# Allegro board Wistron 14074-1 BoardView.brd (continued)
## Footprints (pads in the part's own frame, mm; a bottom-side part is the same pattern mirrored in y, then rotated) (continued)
BSH-03001-FDA
  round 0.254 hole 1.016 unplated: (-10.065,0) (10.065,0)
  rect 0.279x2.769 smd: 1(-7.25,-5.526) 2(-7.25,0.198) 3(-6.75,-5.526) 4(-6.75,0.198) 5(-6.25,-5.526) 6(-6.25,0.198) 7(-5.751,-5.526) 8(-5.751,0.198) 9(-5.25,-5.526) 10(-5.25,0.198) 11(-4.75,-5.526) 12(-4.75,0.198) 13(-4.249,-5.526) 14(-4.249,0.198) 15(-3.75,-5.526) 16(-3.75,0.198) 17(-3.25,-5.526) 18(-3.25,0.198) 19(-2.75,-5.526) 20(-2.75,0.198) 21(-2.25,-5.526) 22(-2.25,0.198) 23(-1.75,-5.526) 24(-1.75,0.198) 25(-1.25,-5.526) 26(-1.25,0.198) 27(-0.751,-5.526) 28(-0.751,0.198) 29(-0.25,-5.526) 30(-0.25,0.198) 31(0.25,-5.526) 32(0.25,0.198) 33(0.751,-5.526) 34(0.751,0.198) 35(1.25,-5.526) 36(1.25,0.198) 37(1.75,-5.526) 38(1.75,0.198) 39(2.25,-5.526) 40(2.25,0.198) 41(2.75,-5.526) 42(2.75,0.198) 43(3.25,-5.526) 44(3.25,0.198) 45(3.75,-5.526) 46(3.75,0.198) 47(4.249,-5.526) 48(4.249,0.198) 49(4.75,-5.526) 50(4.75,0.198) 51(5.25,-5.526) 52(5.25,0.198) 53(5.751,-5.526) 54(5.751,0.198) 55(6.25,-5.526) 56(6.25,0.198) 57(6.75,-5.526) 58(6.75,0.198) 59(7.25,-5.526) 60(7.25,0.198)
C402-TO0D2H26
  custom 0.152x0.152 smd: 1(0,0.457) 2(0,-0.457)
C402H20
  custom 0.152x0.152 smd: 1(0,0.445) 2(0,-0.445)
C402H22
  custom 0.152x0.152 smd: 1(0,0.445) 2(0,-0.445)
C402H24
  custom 0.152x0.152 smd: 1(0,0.445) 2(0,-0.445)
C603
  custom 0.216x0.216 smd: 1(0,0.762) 2(0,-0.762)
C603H36
  custom 0.216x0.216 smd: 1(0,0.762) 2(0,-0.762)
C603H38
  custom 0.216x0.216 smd: 1(0,0.762) 2(0,-0.762)
C603H40
  custom 0.216x0.216 smd: 1(0,0.762) 2(0,-0.762)
C805H54
  rect 1.397x1.143 smd: 1(0,0.965) 2(0,-0.965)
C805H56
  rect 1.397x1.143 smd: 1(0,0.965) 2(0,-0.965)
C805H58
  rect 1.397x1.143 smd: 1(0,0.965) 2(0,-0.965)
C4201WV0-B2X12P
  round 2.184 hole 1.422: 1(-23.1,2.75) 2(-18.9,2.75) 3(-14.7,2.75) 4(-10.5,2.75) 5(-6.3,2.75) 6(-2.1,2.75) 7(2.1,2.75) 8(6.3,2.75) 9(10.5,2.75) 10(14.7,2.75) 11(18.9,2.75) 12(23.1,2.75) 13(-23.1,-2.75) 14(-18.9,-2.75) 15(-14.7,-2.75) 16(-10.5,-2.75) 17(-6.3,-2.75) 18(-2.1,-2.75) 19(2.1,-2.75) 20(6.3,-2.75) 21(10.5,-2.75) 22(14.7,-2.75) 23(18.9,-2.75) 24(23.1,-2.75)
CON2C
  custom 0.171x0.171 smd: 1(0,0.533) 2(0,-0.533)
CON2O-U
  custom 0.159x0.159 smd: 1(0,0.254) 2(0,-0.254)
CT7343H83
  rect 2.413x2.286 smd: 1(0,3.15) 2(0,-3.15)
D1608AK-UH28
  rect 0.559x0.711 smd: A(0,0.889) K(0,-0.889)
D5436AKH97
  rect 2.286x2.032 smd: A(0,2.438) K(0,-2.438)
DFN10G3-G265175H32
  rect 0.305x0.914 smd: 1(1,1.549) 2(0.5,1.549) 3(0,1.549) 4(-0.5,1.549) 5(-1,1.549) 6(-1,-1.549) 7(-0.5,-1.549) 8(0,-1.549) 9(0.5,-1.549) 10(1,-1.549)
  rect 2.642x1.753 smd: 11(0,0)
DFN10G2510H26
  rect 0.305x0.787 smd: 1(1,0.494) 5(-1,0.494) 6(-1,-0.494) 10(1,-0.494)
  rect 0.254x0.787 smd: 2(0.521,0.494) 4(-0.521,0.494) 7(-0.521,-0.494) 9(0.521,-0.494)
  rect 0.025x0.025 smd: 3(0,0.494)
  rect 0.406x1.753 smd: 8(0,-0.494)
DZ11AA1-H5W7-4F
  round 1.448 hole 1.041: 1(-4.326,-2) 2(-2.036,-2) 3(0.254,-2) 4(2.544,-2) 5(4.834,-2) 6(-5.471,0) 7(-3.181,0) 8(-0.892,0) 9(1.4,0) 10(3.689,0) 11(-4.326,2) 12(-2.036,2) 13(0.254,2) 14(2.544,2) 15(4.834,2)
  round 3.454 hole 3.048: 16(-12.496,0) 17(12.496,0)
ECAP-80D5H493
  rect 1.397x1.397 hole 0.991: 1(0,-1.016)
  round 1.397 hole 0.991: 2(0,1.016)
ECAP-100D6D3H237
  rect 1.397x1.397 hole 0.991: 1(0,-1.27)
  round 1.397 hole 0.991: 2(0,1.27)
ECAP-100D6D3H375
  rect 1.397x1.397 hole 0.991: 1(0,-1.27)
  round 1.397 hole 0.991: 2(0,1.27)
ECAP-100D6D3H473
  rect 1.397x1.397 hole 0.991: 1(0,-1.27)
  round 1.397 hole 0.991: 2(0,1.27)
ECAP-138D8-UH355
  rect 1.397x1.397 hole 0.991: 1(0,-1.75)
  round 1.397 hole 0.991: 2(0,1.75)
GAP-CLOSE-PWR-3
  rect 0.66x0.762 smd: 1(-0.305,0) 2(0.305,0)
GENS315R158-8-F-A
  round 0.254 hole 4.013 unplated: (0,0)
  round 0.864 hole 0.508: 1(-0.634,3.189) 2(-2.703,1.806) 3(-3.189,-0.634) 4(-1.806,-2.703) 5(0.634,-3.189) 6(2.703,-1.806) 7(3.189,0.634) 8(1.806,2.703)
HF1004E
  round 1.549 hole 1.143: 1(3.81,0) 2(1.27,0) 3(-1.27,0) 4(-3.81,0)
L603H38
  custom 0.216x0.216 smd: 1(0,0.762) 2(0,-0.762)
L3030-3009-2H40
  rect 3.251x1.524 smd: 1(0,1.108) 2(0,-1.108)
L125100-4P-1H28
  rect 0.762x0.432 smd: 1(0.625,0.341) 2(-0.625,0.341) 3(-0.625,-0.341) 4(0.625,-0.341)
L125100-4P-4H24
  rect 0.762x0.432 smd: 1(-0.625,0.341) 2(0.625,0.341) 3(0.625,-0.341) 4(-0.625,-0.341)
L125100-4P-5H24
  rect 0.457x0.838 smd: 1(-0.326,0.587) 2(0.326,0.587) 3(-0.326,-0.587) 4(0.326,-0.587)
L686647-127318H119
  rect 3.683x2.413 smd: 1(0,2.986) 2(0,-2.986)
LFDFN10G3-G2619H40
  rect 0.305x0.508 smd: 1(1,1.551) 2(0.5,1.551) 3(0,1.551) 4(-0.5,1.551) 5(-1,1.551) 6(-1,-1.551) 7(-0.5,-1.551) 8(0,-1.551) 9(0.5,-1.551) 10(1,-1.551)
  rect 2.591x1.778 smd: 11(0,0)
LFQFN28J4-G2D7-UH40
  rect 0.203x0.584 smd: 1(1.2,1.86) 2(0.8,1.86) 3(0.4,1.86) 4(0,1.86) 5(-0.4,1.86) 6(-0.8,1.86) 7(-1.2,1.86) 15(-1.2,-1.86) 16(-0.8,-1.86) 17(-0.4,-1.86) 18(0,-1.86) 19(0.4,-1.86) 20(0.8,-1.86) 21(1.2,-1.86)
  rect 0.584x0.203 smd: 8(-1.86,1.2) 9(-1.86,0.8) 10(-1.86,0.4) 11(-1.86,0) 12(-1.86,-0.4) 13(-1.86,-0.8) 14(-1.86,-1.2) 22(1.86,-1.2) 23(1.86,-0.8) 24(1.86,-0.4) 25(1.86,0) 26(1.86,0.4) 27(1.86,0.8) 28(1.86,1.2)
  rect 2.692x2.692 smd: 29(0,0)
LQFP64H63
  rect 0.203x1.524 smd: 1(3,4.242) 2(2.6,4.242) 3(2.2,4.242) 4(1.8,4.242) 5(1.4,4.242) 6(0.999,4.242) 7(0.599,4.242) 8(0.199,4.242) 9(-0.199,4.242) 10(-0.599,4.242) 11(-0.999,4.242) 12(-1.4,4.242) 13(-1.8,4.242) 14(-2.2,4.242) 15(-2.6,4.242) 16(-3,4.242) 33(-3,-4.242) 34(-2.6,-4.242) 35(-2.2,-4.242) 36(-1.8,-4.242) 37(-1.4,-4.242) 38(-0.999,-4.242) 39(-0.599,-4.242) 40(-0.199,-4.242) 41(0.199,-4.242) 42(0.599,-4.242) 43(0.999,-4.242) 44(1.4,-4.242) 45(1.8,-4.242) 46(2.2,-4.242) 47(2.6,-4.242) 48(3,-4.242)
  rect 1.524x0.203 smd: 17(-4.242,3) 18(-4.242,2.6) 19(-4.242,2.2) 20(-4.242,1.8) 21(-4.242,1.4) 22(-4.242,0.999) 23(-4.242,0.599) 24(-4.242,0.199) 25(-4.242,-0.199) 26(-4.242,-0.599) 27(-4.242,-0.999) 28(-4.242,-1.4) 29(-4.242,-1.8) 30(-4.242,-2.2) 31(-4.242,-2.6) 32(-4.242,-3) 49(4.242,-3) 50(4.242,-2.6) 51(4.242,-2.2) 52(4.242,-1.8) 53(4.242,-1.4) 54(4.242,-0.999) 55(4.242,-0.599) 56(4.242,-0.199) 57(4.242,0.199) 58(4.242,0.599) 59(4.242,0.999) 60(4.242,1.4) 61(4.242,1.8) 62(4.242,2.2) 63(4.242,2.6) 64(4.242,3)
NTC-402H22-U
  custom 0.14x0.14 smd: 1(0,0.445) 2(0,-0.445)
NTC-402H24-U
  custom 0.14x0.14 smd: 1(0,0.445) 2(0,-0.445)
OSC-3225-4P-4H30
  rect 1.397x1.067 smd: 1(-1.171,-0.756) 2(1.171,-0.756) 3(1.171,0.756) 4(-1.171,0.756)
OSC-3225-4P-4H36
  rect 1.397x1.067 smd: 1(-1.171,-0.756) 2(1.171,-0.756) 3(1.171,0.756) 4(-1.171,0.756)
PFPCC48-1H63
  rect 0.305x1.524 smd: 1(2.752,4.242) 2(2.252,4.242) 3(1.751,4.242) 4(1.251,4.242) 5(0.751,4.242) 6(0.25,4.242) 7(-0.25,4.242) 8(-0.751,4.242) 9(-1.251,4.242) 10(-1.751,4.242) 11(-2.252,4.242) 12(-2.752,4.242) 25(-2.752,-4.242) 26(-2.252,-4.242) 27(-1.751,-4.242) 28(-1.251,-4.242) 29(-0.751,-4.242) 30(-0.25,-4.242) 31(0.25,-4.242) 32(0.751,-4.242) 33(1.251,-4.242) 34(1.751,-4.242) 35(2.252,-4.242) 36(2.752,-4.242)
  rect 1.524x0.305 smd: 13(-4.242,2.752) 14(-4.242,2.252) 15(-4.242,1.751) 16(-4.242,1.251) 17(-4.242,0.751) 18(-4.242,0.25) 19(-4.242,-0.25) 20(-4.242,-0.751) 21(-4.242,-1.251) 22(-4.242,-1.751) 23(-4.242,-2.252) 24(-4.242,-2.752) 37(4.242,-2.752) 38(4.242,-2.252) 39(4.242,-1.751) 40(4.242,-1.251) 41(4.242,-0.751) 42(4.242,-0.25) 43(4.242,0.25) 44(4.242,0.751) 45(4.242,1.251) 46(4.242,1.751) 47(4.242,2.252) 48(4.242,2.752)
POLYSW-2114H30
  rect 1.6x0.965 smd: 1(0,0.94) 2(0,-0.94)
PPA12635GD210F
  round 2.159 hole 1.397: 1(-18.9,2.75) 2(-14.7,2.75) 3(-10.5,2.75) 4(-6.3,2.75) 5(-2.101,2.75) 6(2.101,2.75) 7(6.3,2.75) 8(10.5,2.75) 9(14.7,2.75) 10(18.9,2.75) 11(-18.9,-2.75) 12(-14.7,-2.75) 13(-10.5,-2.75) 14(-6.3,-2.75) 15(-2.101,-2.75) 16(2.101,-2.75) 17(6.3,-2.75) 18(10.5,-2.75) 19(14.7,-2.75) 20(18.9,-2.75)
PPAK-8P-3030H40
  rect 0.406x0.914 smd: 1(-0.975,-2.251) 2(-0.325,-2.251) 3(0.325,-2.251) 4(0.975,-2.251)
  rect 3.404x2.616 smd: 5(0,0)
  rect 0.025x0.025 smd: 6(1.079,0.851) 7(-0.368,0.876) 8(-1.13,0.838)
PPAK-8P-3232H40
  rect 0.406x0.914 smd: 1(-0.975,-2.396) 2(-0.325,-2.396) 3(0.325,-2.396) 4(0.975,-2.396)
  rect 3.353x2.692 smd: 5(0,0)
  rect 0.025x0.025 smd: 6(0.65,0.838) 7(0,0.838) 8(-0.65,0.838)
PPAK-8P-5262H40
  rect 0.762x1.448 smd: 1(-1.905,-3.684) 2(-0.635,-3.684) 3(0.635,-3.684) 4(1.905,-3.684)
  rect 5.512x5.309 smd: 5(0,0)
  rect 0.025x0.025 smd: 6(0.635,2.146) 7(-0.635,2.146) 8(-1.905,2.146)
PU2B1B5-PRTB
  round 1.346 hole 0.94: 1(-3.5,4.63) 2(-1,4.63) 3(1,4.63) 4(3.5,4.63) 5(4,6.13) 6(2,6.13) 7(0,6.13) 8(-2,6.13) 9(-4,6.13) 10(-3.5,7.83) 11(-1,7.83) 12(1,7.83) 13(3.5,7.83) 14(4,9.33) 15(2,9.33) 16(0,9.33) 17(-2,9.33) 18(-4,9.33)
  round 2.718 hole 2.311: G1(-9.35,0) G2(9.35,0) G3(-6.57,2.63) G4(6.57,2.63) G5(-6.57,8.31) G6(6.57,8.31) G7(-9.35,11.6) G8(9.35,13.34)
  round 1.321 hole 0.914: L11(7.2,18.81) L12(4.66,18.81) L13(-4.66,18.81) L14(-7.2,18.81) R1(5.715,13.43) R2(4.445,15.97) R3(3.175,13.43) R4(1.905,15.97) R5(0.635,13.43) R6(-0.635,15.97) R7(-1.905,13.43) R8(-3.175,15.97) R9(-4.445,13.43) R10(-5.715,15.97)
QFN20-G1D75H32
  rect 0.203x0.914 smd: 1(0.8,1.551) 2(0.4,1.551) 3(0,1.551) 4(-0.4,1.551) 5(-0.8,1.551) 11(-0.8,-1.551) 12(-0.4,-1.551) 13(0,-1.551) 14(0.4,-1.551) 15(0.8,-1.551)
  rect 0.914x0.203 smd: 6(-1.551,0.8) 7(-1.551,0.4) 8(-1.551,0) 9(-1.551,-0.4) 10(-1.551,-0.8) 16(1.551,-0.8) 17(1.551,-0.4) 18(1.551,0) 19(1.551,0.4) 20(1.551,0.8)
  rect 1.753x1.753 smd: 21(0,0)
QFN28-G3D75H32
  rect 0.305x0.914 smd: 1(1.5,2.551) 2(1,2.551) 3(0.5,2.551) 4(0,2.551) 5(-0.5,2.551) 6(-1,2.551) 7(-1.5,2.551) 15(-1.5,-2.551) 16(-1,-2.551) 17(-0.5,-2.551) 18(0,-2.551) 19(0.5,-2.551) 20(1,-2.551) 21(1.5,-2.551)
  rect 0.914x0.305 smd: 8(-2.551,1.5) 9(-2.551,1) 10(-2.551,0.5) 11(-2.551,0) 12(-2.551,-0.5) 13(-2.551,-1) 14(-2.551,-1.5) 22(2.551,-1.5) 23(2.551,-1) 24(2.551,-0.5) 25(2.551,0) 26(2.551,0.5) 27(2.551,1) 28(2.551,1.5)
  rect 3.759x3.759 smd: 29(0,0)
QFN32-G3D6H40
  rect 0.305x0.914 smd: 1(1.75,2.559) 8(-1.75,2.559) 17(-1.75,-2.559) 24(1.75,-2.559)
  rect 0.305x1.016 smd: 2(1.25,2.508) 3(0.75,2.508) 4(0.25,2.508) 5(-0.25,2.508) 6(-0.75,2.508) 7(-1.25,2.508) 18(-1.25,-2.508) 19(-0.75,-2.508) 20(-0.25,-2.508) 21(0.25,-2.508) 22(0.75,-2.508) 23(1.25,-2.508)
  rect 0.914x0.305 smd: 9(-2.559,1.75) 16(-2.559,-1.75) 25(2.559,-1.75) 32(2.559,1.75)
  rect 1.016x0.305 smd: 10(-2.508,1.25) 11(-2.508,0.75) 12(-2.508,0.25) 13(-2.508,-0.25) 14(-2.508,-0.75) 15(-2.508,-1.25) 26(2.508,-1.25) 27(2.508,-0.75) 28(2.508,-0.25) 29(2.508,0.25) 30(2.508,0.75) 31(2.508,1.25)
  rect 3.556x3.556 smd: 33(0,0)
QFN32J4-G2D85H36
  rect 0.203x0.864 smd: 1(1.4,2.085) 2(1,2.085) 3(0.6,2.085) 4(0.2,2.085) 5(-0.2,2.085) 6(-0.6,2.085) 7(-1,2.085) 8(-1.4,2.085) 17(-1.4,-2.085) 18(-1,-2.085) 19(-0.6,-2.085) 20(-0.2,-2.085) 21(0.2,-2.085) 22(0.6,-2.085) 23(1,-2.085) 24(1.4,-2.085)
  rect 0.864x0.203 smd: 9(-2.085,1.4) 10(-2.085,1) 11(-2.085,0.6) 12(-2.085,0.2) 13(-2.085,-0.2) 14(-2.085,-0.6) 15(-2.085,-1) 16(-2.085,-1.4) 25(2.085,-1.4) 26(2.085,-1) 27(2.085,-0.6) 28(2.085,-0.2) 29(2.085,0.2) 30(2.085,0.6) 31(2.085,1) 32(2.085,1.4)
  rect 2.845x2.845 smd: 33(0,0)
R402H14
  custom 0.14x0.14 smd: 1(0,0.445) 2(0,-0.445)
R402H16
  custom 0.14x0.14 smd: 1(0,0.445) 2(0,-0.445)
R603H22
  custom 0.216x0.216 smd: 1(0,0.762) 2(0,-0.762)
R805H24
  rect 1.397x1.143 smd: 1(0,0.965) 2(0,-0.965)
R2512-1U1H36
  rect 3.429x2.87 smd: 1(0,2.645) 2(0,-2.645)
SC70-6H44
  rect 0.406x1.016 smd: 1(-0.65,-0.94) 2(0,-0.94) 3(0.65,-0.94) 4(0.65,0.94) 5(0,0.94) 6(-0.65,0.94)
SE361414H241
  rect 1.372x3.607 smd: 1(0,2.499) 2(0,-2.499)
SE361416H178
  rect 1.422x3.556 smd: 1(0,2.574) 2(0,-2.574)
SKT-HDMI23-150122-9
  rect 0.305x2.591 smd: 1(4.5,0.76) 2(4,0.76) 3(3.5,0.76) 4(3,0.76) 5(2.5,0.76) 6(2,0.76) 7(1.5,0.76) 8(1,0.76) 9(0.5,0.76) 10(0,0.76) 11(-0.5,0.76) 12(-1,0.76) 13(-1.5,0.76) 14(-2,0.76) 15(-2.5,0.76) 16(-3,0.76) 17(-3.5,0.76) 18(-4,0.76) 19(-4.5,0.76)
  oval 1.626x3.429 hole 0.914x2.718: 20(7.25,0) 21(-7.25,0)
  oval 1.626x2.819 hole 0.914x2.108: 22(7.25,-5.96) 23(-7.25,-5.96)
SKT-SOIC8-092117H235
  rect 0.508x1.702 smd: 1(1.905,4.1) 2(0.635,4.1) 3(-0.635,4.1) 4(-1.905,4.1) 5(-1.905,-4.1) 6(-0.635,-4.1) 7(0.635,-4.1) 8(1.905,-4.1)
SKT-USB12-157183
  round 1.346 hole 0.94: 1(-3.5,2.71) 2(-1,2.71) 3(1,2.71) 4(3.5,2.71) 5(-3.5,5.33) 6(-1,5.33) 7(1,5.33) 8(3.5,5.33)
  round 2.718 hole 2.311: 9(-6.57,0) 10(6.57,0) 11(-6.57,5.68) 12(6.57,5.68)
SMD49-6914-0403H56
  rect 1.168x0.559 smd: 1(-3.38,-0.427) 2(3.38,-0.427) 3(3.38,0.427) 4(-3.38,0.427)
SMD-ARES4H18
  rect 0.356x0.66 smd: 1(-0.325,-0.599) 2(0.325,-0.599) 3(0.325,0.599) 4(-0.325,0.599)
SMD-ARES4H20
  rect 0.356x0.66 smd: 1(-0.325,-0.599) 2(0.325,-0.599) 3(0.325,0.599) 4(-0.325,0.599)
SMD-OSC8H52
  rect 1.803x1.6 smd: 1(-1.469,-1.4) 2(1.469,-1.4) 3(1.469,1.4) 4(-1.469,1.4)
SMD-TO-252-4H100
  rect 1.6x2.997 smd: 1(-2.286,0) 3(2.286,0)
  rect 6.756x6.756 smd: 2(0,6.807)
SMD-TO-252-DGS6698H99
  rect 6.172x5.588 smd: D(0,6.808)
  rect 1.295x2.438 smd: G(-2.35,0) S(2.35,0)
SOD323AKH38
  rect 0.559x1.016 smd: A(0,1.143) K(0,-1.143)
SOD323AKH40
  rect 0.559x1.016 smd: A(0,1.143) K(0,-1.143)
SOD882-10D6-1H20
  custom 0.114x0.114 smd: 1(0,0.445) 2(0,-0.445)
SOIC8-1H86
  rect 0.635x1.651 smd: 1(-1.905,-3.493) 2(-0.635,-3.493) 3(0.635,-3.493) 4(1.905,-3.493) 5(1.905,3.493) 6(0.635,3.493) 7(-0.635,3.493) 8(-1.905,3.493)
SOIC8-G3530H63
  rect 0.635x1.651 smd: 1(-1.905,-2.555) 2(-0.635,-2.555) 3(0.635,-2.555) 4(1.905,-2.555) 5(1.905,2.555) 6(0.635,2.555) 7(-0.635,2.555) 8(-1.905,2.555)
  rect 3.505x2.997 smd: 9(0,0)
SOIC8H69
  rect 0.635x1.651 smd: 1(-1.905,-2.54) 2(-0.635,-2.54) 3(0.635,-2.54) 4(1.905,-2.54) 5(1.905,2.54) 6(0.635,2.54) 7(-0.635,2.54) 8(-1.905,2.54)
SON14J3020-G2610H34
  rect 0.025x0.025 smd: 1(1.2,1.105) 6(-0.8,1.105) 9(-0.8,-1.105) 14(1.2,-1.105)
  custom 0.151x0.151 smd: 2(0.8,1.105) 7(-1.2,1.105) 8(-1.2,-1.105) 13(0.8,-1.105)
  rect 0.203x0.813 smd: 3(0.4,1.105) 4(0,1.105) 5(-0.4,1.105) 10(-0.4,-1.105) 11(0,-1.105) 12(0.4,-1.105)
  rect 2.591x0.889 smd: 15(0,0)
SOT23-2D4-312H44
  custom 0.191x0.191 smd: 1(-0.984,-0.953) 2(0.984,-0.953) 3(0,0.953)
SOT23-2D4-312H46
  custom 0.191x0.191 smd: 1(-0.984,-0.953) 2(0.984,-0.953) 3(0,0.953)
SOT23-2D4-312H48
  custom 0.191x0.191 smd: 1(-0.984,-0.953) 2(0.984,-0.953) 3(0,0.953)
SOT23-8PH36
  rect 0.356x1.016 smd: 1(-0.975,-1.346) 2(-0.325,-1.346) 3(0.325,-1.346) 4(0.974,-1.346) 5(0.974,1.346) 6(0.325,1.346) 7(-0.325,1.346) 8(-0.975,1.346)
SOT23CBE2D4H44
  custom 0.191x0.191 smd: B(-0.984,-0.953) C(0,0.953) E(0.984,-0.953)
SOT23DGS2D4H44
  custom 0.191x0.191 smd: D(0,0.953) G(-0.984,-0.953) S(0.984,-0.953)
SOT23DGS2D4H48
  custom 0.191x0.191 smd: D(0,0.953) G(-0.984,-0.953) S(0.984,-0.953)
SOT23DGS2D8H50
  custom 0.254x0.254 smd: D(0,1.118) G(-1.016,-1.118) S(1.016,-1.118)
SOT-6H58
  rect 0.584x1.016 smd: 1(-0.953,-1.346) 2(0,-1.346) 3(0.953,-1.346) 4(0.953,1.346) 5(0,1.346) 6(-0.953,1.346)
SOT-23-5H52
  rect 0.508x1.524 smd: 1(-0.95,-1.143) 2(0,-1.143) 3(0.95,-1.143) 4(0.95,1.143) 5(-0.95,1.143)
SOT-23-5H56
  rect 0.508x1.524 smd: 1(-0.95,-1.143) 2(0,-1.143) 3(0.95,-1.143) 4(0.95,1.143) 5(-0.95,1.143)
SOT-23-9H44
  custom 0.178x0.178 smd: 1(-0.95,-0.999) 2(0.95,-0.999) 3(0,0.999)
SOT-23-10H44
  rect 0.762x1.143 smd: 1(-0.984,-0.953) 2(0.984,-0.953) 3(0,0.953)
SOT-363H44
  rect 0.406x1.016 smd: 1(-0.65,-0.94) 2(0,-0.94) 3(0.65,-0.94) 4(0.65,0.94) 5(0,0.94) 6(-0.65,0.94)
STF256R109H99
  round 6.502 hole 2.769: 1(0,0)
T11-0063-1A40-0-U
  round 1.422 hole 1.016: 1(7.62,1.27) 2(7.62,-1.27) 3(5.08,1.27) 4(5.08,-1.27) 5(2.54,1.27) 6(2.54,-1.27) 7(0,1.27) 8(0,-1.27) 9(-2.54,1.27) 11(-5.08,1.27) 12(-5.08,-1.27) 13(-7.62,1.27) 14(-7.62,-1.27)
  rect 0.025x0.025 smd: 10(-2.54,-1.27)
TPAD14-OP
  round 0.356 smd: 1(0,0)
TPAD24
  round 0.61 smd: 1(0,0)
TPAD28
  round 0.711 smd: 1(0,0)
unnamed#2
  round 1.016 smd: (0,0)

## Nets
3VSB_DET: R2050.1 SIO1.27
5V_DDC_HDMI11: C5601.2 D3.2 R1.1 R5601.1
5V_DDC_HDMI12: C5602.2 D3.1 ED2303.5 R2.1 R5601.2
5V_DDC_HDMI21: C5603.2 D4.2 R5602.1 R9689.1
5V_DDC_HDMI22: C5604.2 D4.1 ED2304.5 R5602.2 R9690.1
5V_DUAL: C3508.1 C3509.1 C4301.2 D2202.A ED3201.2 L2202.2 PC5035.1 PD5001.A PL4702.2 PL5002.2 PL5003.2 PL5102.2 PL5103.2 PR4701.1 PR4712.1 PR4802.2 PR4805.1 PR5013.1 PR5024.1 PR5104.1 PR5115.1 PR5209.2 PR5231.1 PU5004.12 Q3404.E Q3507.D Q3508.D Q3509.D R3418.1 R3519.2 R3520.2 R4601.1 R4611.1 R4613.1 R5002.2 R9884.1 RN5411.4(B) U2901.1 U2901.2 U2903.1 U2903.2 U3701.5 U3702.5 U3703.5 U3801.5 U4301.1 U4301.2 U4301.3 U6510.1 U6510.2 U6511.1 U6511.2
5V_DUAL_EN1: Q3512.G Q3514.D Q3516.G Q4303.3 R3522.2
5V_DUAL_EN2: Q4303.5 R3525.1
5V_DUAL_EN3: Q4303.4 Q4303.6
5V_DUAL_EN4: Q4303.2 R3526.1
5V_DUAL_EN5: C3507.1 Q3507.G R3502.1
5V_DUAL_EN6: C3504.2 C3506.1 C3508.2 C3509.2 Q3508.G Q3509.G R3501.1
5V_DUAL_EN_5VSB: Q3516.D R3501.2 R3516.2 R3524.2
5V_DUAL_EN_12V: Q3512.D R3502.2 R3521.1 R3523.1
5V_HDMI: C2301.1 C15173.1 F2301.2 HDMI1.18 HDMI2.18 R9699.2
5V_HUB: R4601.2 U4601.27
5V_S0: ATX1.4 ATX1.6 ATX1.21 ATX1.22 ATX1.23 ATX2.4 ATX2.6 ATX2.19 ATX2.20 BUZ1.1 C1902.2 C2303.1 C3507.2 C5410.1 C5415.1 C6001.2 C6003.1 D3.3 D4.3 D2402.A EC3401.1 EC3409.2 F2301.1 F2402.2 PR4428.1 PR4430.1 PR4528.1 PR4530.1 Q3401.E Q3507.S Q6514.G Q6519.G R2008.2 R3402.2 R3405.1 R3425.1 R3521.2 R6564.2 SATAP1.1 SATAP1.2 U5401.8 U5401.9
5V_S0_VGA: C2415.1 C15157.1 ED6520.5 F2402.1 R9699.1 VGA1.9
5V_SB: ATX1.9 ATX2.9 C3407.1 C3504.1 C5413.1 C5418.1 PC3601.1 PC3602.1 PR4222.2 PR4907.2 PR4909.2 PR4913.2 PR4915.2 PU3601.3 Q3508.S Q3509.S R3403.1 R3411.1 R3413.1 R3516.1 R3517.1 R3519.1 R3520.1 R3522.1 R3524.1 R4308.1 U4301.5 U4301.6 U4301.7 U4301.8 U5401.4 U5401.6 U5401.7
5VSB_CTRL#: R2048.1 R9708.2 SIO1.5
12V_S0: ATX1.10 ATX1.11 ATX2.10 C1901.2 C1909.1 C1910.1 C1911.1 C1912.1 C1913.1 C2501.1 C3301.1 C3302.1 C6002.2 C6004.1 EC3414.1 PCIE16.A2 PCIE16.A3 PCIE16.B1 PCIE16.B2 PCIE16.B3 PL4402.1 PL4502.1 PR4429.1 PR4529.1 PR5007.2 PR5008.2 PR5009.2 Q2501.E Q2502.E R2003.2 R2508.1 R2509.1 R2517.1 R3423.1 R3523.2 SATAP1.5 SATAP1.6 TC1901.1
12V_VIN: PC5007.1 PC5011.1 PC5012.1 PL5004.2 PL5007.2 PQ5003.5 PQ5003.6 PQ5003.7 PQ5003.8 PT5004.1
19V_ADP: PC4201.1 PL4403.1 PL4601.1 PL4703.2 PL4801.2 PL4901.1 PL4902.1 PL5004.1 PL5006.2 PL5007.1 PR4209.1 PR4217.2 PR4219.1 PR4220.2 PR4221.2 PR4224.2 PR4226.2 PR4434.1 PR4601.1 PU4202.8 PU4203.8 R4003.1 R4301.1 R4303.1
+3VL: PG4904.2
+5V_PWR: PC4910.1 PG4903.1 PL4904.2 PR4907.1 PR4909.1 PR4913.1 PR4915.1 PT4903.1
+5VL: PG4901.2 PR4917.1
+12V: PC5010.1 PL5005.2 PR5004.1 PR5005.1 PR5007.1 PR5008.1 PR5009.1 PR5018.2 PT5005.1
+VCCCFIOAZA_1P80: AUDIO1.9 C1102.1 C2207.1 CPU1.AF4 CPU1.AH4 R2733.2 R2734.2 R6526.2 R6532.2 R9845.2
+VCCCLKDDR_1P24_1P35: C1119.1 CPU1.AM25 R6528.1
+VCCPADCF3SI0_1P8_3P3: C1126.1 C1127.1 CPU1.E1 CPU1.E2 R6527.2 R6533.2
+VCCSFRPLLDDR_1P24_1P35: C1118.1 CPU1.AN27 R6529.1
-12V: ATX1.14 ATX2.12 EC3412.1
AGND: AUDH1.1 AUDIO1.26 AUDIO1.42 AUDR1.1 AUDR1.4 AUDR1.24 AUDR1.34 C2201.2 C2202.2 C2203.2 C2204.2 C2205.2 C2211.1 C2212.2 C2215.2 C2216.2 C2217.2 C2218.2 C2219.2 C2227.1 C2228.1 C2230.2 C2231.2 C2701.2 C2702.2 C2703.2 C2704.2 C2705.2 C2706.2 D2701.K D2702.K D2703.K D2704.3 D2705.3 D2706.3 Q2701.1 Q2701.4 Q2702.1 Q2702.4 Q2703.1 Q2703.4 Q2704.1 Q2704.4 Q2705.1 Q2705.4 R2203.2 R2213.2 R2228.2 R2230.2 R2231.2 R2709.2 R2710.2 R9798.2 R9799.2 R9800.2 R9801.2
AVDD2: AUDIO1.25 AUDIO1.38 C2202.1 C2203.1 C2204.1 C2205.1
GND: ATX1.3 ATX1.5 ATX1.7 ATX1.15 ATX1.17 ATX1.18 ATX1.19 ATX1.24 ATX2.3 ATX2.5 ATX2.7 ATX2.13 ATX2.15 ATX2.16 ATX2.17 AUDIO1.7 AUDR1.G1 AUDR1.G2 AUDR1.G3 AUDR1.G4 BT1.2 C20.2 C501.2 C502.2 C503.2 C504.2 C1001.2 C1002.2 C1003.2 C1004.2 C1005.2 C1006.2 C1007.2 C1008.2 C1009.2 C1010.2 C1011.2 C1012.2 C1013.2 C1017.2 C1018.2 C1020.2 C1022.2 C1024.2 C1025.2 C1026.2 C1027.2 C1030.2 C1031.2 C1032.2 C1033.2 C1034.2 C1035.2 C1037.2 C1040.2 C1041.2 C1042.2 C1043.2 C1044.2 C1045.2 C1046.2 C1047.2 C1048.2 C1049.2 C1056.2 C1057.2 C1102.2 C1103.2 C1104.2 C1105.2 C1108.2 C1110.2 C1111.2 C1113.2 C1114.2 C1115.2 C1116.2 C1118.2 C1119.2 C1120.2 C1121.2 C1122.2 C1123.2 C1124.2 C1126.2 C1127.2 C1128.2 C1130.2 C1132.2 C1133.2 C1134.2 C1137.2 C1138.2 C1201.2 C1202.2 C1203.2 C1204.2 C1205.2 C1206.2 C1207.2 C1208.2 C1209.2 C1210.2 C1211.2 C1212.2 C1213.2 C1214.2 C1215.2 C1216.2 C1217.2 C1218.2 C1219.2 C1220.2 C1221.2 C1222.2 C1223.2 C1224.2 C1225.2 C1226.2 C1227.2 C1230.2 C1231.2 C1301.2 C1302.2 C1303.2 C1304.2 C1305.2 C1306.2 C1307.2 C1308.2 C1309.2 C1310.2 C1311.2 C1312.2 C1313.2 C1314.2 C1315.2 C1316.2 C1317.2 C1318.2 C1319.2 C1320.2 C1321.2 C1322.2 C1323.2 C1324.2 C1325.2 C1326.2 C1327.2 C1330.2 C1331.2 C1501.2 C1502.2 C1803.2 C1901.1 C1903.2 C1905.2 C1906.2 C1907.2 C1908.2 C1909.2 C1910.2 C1911.2 C1912.2 C1913.2 C2001.2 C2003.2 C2004.2 C2005.2 C2008.2 C2010.2 C2012.2 C2013.2 C2014.2 C2015.1 C2017.2 C2018.1 C2040.2 C2101.2 C2102.2 C2103.2 C2104.2 C2105.2 C2106.2 C2107.2 C2108.2 C2109.2 C2110.2 C2111.2 C2114.2 C2115.2 C2116.1 C2117.1 C2119.2 C2120.2 C2201.1 C2206.2 C2207.2 C2208.2 C2209.2 C2210.2 C2215.1 C2216.1 C2217.1 C2220.2 C2229.2 C2301.2 C2303.2 C2415.2 C2434.1 C2435.1 C2501.2 C2503.2 C2506.2 C2507.1 C2707.2 C2708.2 C2709.1 C2809.2 C2810.2 C2811.2 C2813.2 C2903.2 C2907.2 C2908.2 C2911.2 C2912.2 C3301.2 C3302.2 C3402.2 C3403.2 C3404.2 C3405.2 C3406.2 C3407.2 C3408.2 C3410.2 C3411.1 C3416.2 C3501.2 C3506.2 C4302.1 C4303.2 C4601.1 C4602.2 C4603.1 C4604.1 C4605.2 C4606.2 C4607.2 C4608.2 C4609.2 C4610.2 C4611.2 C5001.2 C5301.2 C5303.2 C5304.2 C5305.2 C5306.2 C5307.2 C5308.2 C5309.2 C5310.2 C5311.2 C5409.2 C5410.2 C5411.2 C5412.2 C5413.2 C5414.2 C5415.2 C5416.2 C5417.2 C5418.2 C5419.2 C5601.1 C5602.1 C5603.1 C5604.1 C6001.1 C6002.1 C6003.2 C6004.2 C6101.2 C6102.2 C6103.2 C6104.2 C6105.2 C7537.2 C7538.2 C7539.2 C7540.2 C7542.2 C7924.2 C9602.2 C9603.2 C9604.2 C9605.1 C9606.1 C15110.2 C15111.2 C15129.2 C15147.2 C15148.2 C15149.1 C15150.1 C15151.1 C15152.1 C15153.1 C15154.1 C15155.1 C15156.1 C15157.2 C15173.2 C15174.2 C15175.2 C15178.1 C15183.2 C15184.2 C15185.2 C15186.2 C15189.2 C15190.2 C15191.2 C15192.2 CPU1.A5 CPU1.A7 CPU1.A11 CPU1.A15 CPU1.A19 CPU1.A23 CPU1.A31 CPU1.A39 CPU1.A43 CPU1.A47 CPU1.AA16 CPU1.AA27 CPU1.AA38 CPU1.AA53 CPU1.AB4 CPU1.AB6 CPU1.AB10 CPU1.AB12 CPU1.AB13 CPU1.AB14 CPU1.AB42 CPU1.AB47 CPU1.AB50 CPU1.AC16 CPU1.AC29 CPU1.AC33 CPU1.AC35 CPU1.AC38 CPU1.AD4 CPU1.AD21 CPU1.AD30 CPU1.AD32 CPU1.AD36 CPU1.AD44 CPU1.AE1 CPU1.AE6 CPU1.AE8 CPU1.AE9 CPU1.AE11 CPU1.AE12 CPU1.AE14 CPU1.AE40 CPU1.AE42 CPU1.AE43 CPU1.AE45 CPU1.AE46 CPU1.AE48 CPU1.AE50 CPU1.AE53 CPU1.AF10 CPU1.AF24 CPU1.AF25 CPU1.AF32 CPU1.AF38 CPU1.AF47 CPU1.AG25 CPU1.AH9 CPU1.AH10 CPU1.AH12 CPU1.AH13 CPU1.AH14 CPU1.AH41 CPU1.AH42 CPU1.AH44 CPU1.AH47 CPU1.AJ1 CPU1.AJ3 CPU1.AJ16 CPU1.AJ18 CPU1.AJ25 CPU1.AJ51 CPU1.AJ53 CPU1.AK4 CPU1.AK7 CPU1.AK16 CPU1.AK22 CPU1.AK25 CPU1.AK27 CPU1.AK29 CPU1.AK32 CPU1.AK38 CPU1.AK40 CPU1.AK44 CPU1.AK45 CPU1.AK47 CPU1.AK50 CPU1.AM4 CPU1.AM13 CPU1.AM16 CPU1.AM24 CPU1.AM27 CPU1.AM30 CPU1.AM35 CPU1.AM38 CPU1.AM42 CPU1.AM50 CPU1.AN1 CPU1.AN3 CPU1.AN5 CPU1.AN6 CPU1.AN8 CPU1.AN9 CPU1.AN11 CPU1.AN12 CPU1.AN14 CPU1.AN16 CPU1.AN21 CPU1.AN24 CPU1.AN25 CPU1.AN29 CPU1.AN30 CPU1.AN33 CPU1.AN38 CPU1.AN40 CPU1.AN42 CPU1.AN43 CPU1.AN45 CPU1.AN46 CPU1.AN48 CPU1.AN49 CPU1.AN51 CPU1.AN53 CPU1.AP4 CPU1.AP9 CPU1.AP45 CPU1.AP50 CPU1.AT3 CPU1.AT9 CPU1.AT18 CPU1.AT19 CPU1.AT27 CPU1.AT35 CPU1.AT36 CPU1.AT45 CPU1.AT51 CPU1.AU1 CPU1.AU3 CPU1.AU51 CPU1.AU53 CPU1.AV14 CPU1.AV19 CPU1.AV24 CPU1.AV27 CPU1.AV30 CPU1.AV35 CPU1.AV40 CPU1.AW13 CPU1.AW19 CPU1.AW27 CPU1.AW35 CPU1.AW41 CPU1.AY3 CPU1.AY7 CPU1.AY9 CPU1.AY20 CPU1.AY22 CPU1.AY24 CPU1.AY26 CPU1.AY28 CPU1.AY30 CPU1.AY32 CPU1.AY34 CPU1.AY45 CPU1.AY47 CPU1.AY51 CPU1.B2 CPU1.B28 CPU1.B36 CPU1.BA19 CPU1.BA24 CPU1.BA27 CPU1.BA30 CPU1.BA35 CPU1.BB4 CPU1.BB19 CPU1.BB27 CPU1.BB35 CPU1.BB50 CPU1.BC10 CPU1.BC14 CPU1.BC16 CPU1.BC26 CPU1.BC28 CPU1.BC38 CPU1.BC40 CPU1.BC44 CPU1.BD1 CPU1.BD19 CPU1.BD27 CPU1.BD35 CPU1.BD53 CPU1.BE19 CPU1.BE35 CPU1.BF4 CPU1.BF12 CPU1.BF22 CPU1.BF26 CPU1.BF27 CPU1.BF28 CPU1.BF32 CPU1.BF42 CPU1.BF50 CPU1.BG1 CPU1.BG5 CPU1.BG7 CPU1.BG14 CPU1.BG16 CPU1.BG18 CPU1.BG19 CPU1.BG20 CPU1.BG24 CPU1.BG27 CPU1.BG30 CPU1.BG34 CPU1.BG35 CPU1.BG36 CPU1.BG38 CPU1.BG40 CPU1.BG47 CPU1.BG49 CPU1.BG53 CPU1.BH1 CPU1.BH2 CPU1.BH52 CPU1.BJ7 CPU1.BJ11 CPU1.BJ15 CPU1.BJ19 CPU1.BJ23 CPU1.BJ27 CPU1.BJ31 CPU1.BJ35 CPU1.BJ39 CPU1.BJ43 CPU1.BJ47 CPU1.C1 CPU1.C3 CPU1.C20 CPU1.C22 CPU1.C28 CPU1.C30 CPU1.C36 CPU1.C39 CPU1.C47 CPU1.D10 CPU1.D16 CPU1.D24 CPU1.D27 CPU1.D32 CPU1.D38 CPU1.D40 CPU1.D42 CPU1.E19 CPU1.E35 CPU1.E46 CPU1.E51 CPU1.F1 CPU1.F5 CPU1.F19 CPU1.F24 CPU1.F27 CPU1.F32 CPU1.F35 CPU1.G12 CPU1.G14 CPU1.G22 CPU1.G26 CPU1.G28 CPU1.G30 CPU1.H8 CPU1.H19 CPU1.H27 CPU1.H35 CPU1.J18 CPU1.J19 CPU1.J22 CPU1.J27 CPU1.J30 CPU1.J35 CPU1.J38 CPU1.J42 CPU1.J53 CPU1.K4 CPU1.K12 CPU1.K14 CPU1.K16 CPU1.K22 CPU1.K24 CPU1.K30 CPU1.K32 CPU1.K34 CPU1.K36 CPU1.K45 CPU1.K50 CPU1.L1 CPU1.L19 CPU1.L27 CPU1.L35 CPU1.L41 CPU1.M9 CPU1.M14 CPU1.M19 CPU1.M24 CPU1.M27 CPU1.M35 CPU1.M40 CPU1.M45 CPU1.M50 CPU1.N22 CPU1.N24 CPU1.N32 CPU1.N51 CPU1.N53 CPU1.P4 CPU1.P10 CPU1.P19 CPU1.P22 CPU1.P27 CPU1.P32 CPU1.P35 CPU1.P36 CPU1.P42 CPU1.R1 CPU1.T9 CPU1.T14 CPU1.T47 CPU1.U5 CPU1.U6 CPU1.U8 CPU1.U9 CPU1.U11 CPU1.U12 CPU1.U14 CPU1.U18 CPU1.U21 CPU1.U25 CPU1.U29 CPU1.U30 CPU1.U32 CPU1.U33 CPU1.U36 CPU1.U38 CPU1.U40 CPU1.U42 CPU1.U43 CPU1.U45 CPU1.U46 CPU1.U48 CPU1.U49 CPU1.U53 CPU1.V16 CPU1.V21 CPU1.V25 CPU1.V32 CPU1.V38 CPU1.V41 CPU1.V42 CPU1.V44 CPU1.W1 CPU1.Y4 CPU1.Y9 CPU1.Y10 CPU1.Y14 CPU1.Y16 CPU1.Y19 CPU1.Y21 CPU1.Y22 CPU1.Y24 CPU1.Y29 CPU1.Y38 CPU1.Y40 CPU1.Y45 CPU1.Y50 D2202.K DBGH1.8 DBGH1.12 DCIN1.2 DCIN1.3 DCIN1.4 DCIN1.5 DCIN1.6 DIMM1.2 DIMM1.3 DIMM1.8 DIMM1.9 DIMM1.13 DIMM1.14 DIMM1.19 DIMM1.20 DIMM1.25 DIMM1.26 DIMM1.31 DIMM1.32 DIMM1.37 DIMM1.38 DIMM1.43 DIMM1.44 DIMM1.48 DIMM1.49 DIMM1.54 DIMM1.55 DIMM1.60 DIMM1.61 DIMM1.65 DIMM1.66 DIMM1.71 DIMM1.72 DIMM1.127 DIMM1.128 DIMM1.133 DIMM1.134 DIMM1.138 DIMM1.139 DIMM1.144 DIMM1.145 DIMM1.150 DIMM1.151 DIMM1.155 DIMM1.156 DIMM1.161 DIMM1.162 DIMM1.167 DIMM1.168 DIMM1.172 DIMM1.173 DIMM1.178 DIMM1.179 DIMM1.184 DIMM1.185 DIMM1.189 DIMM1.190 DIMM1.195 DIMM1.196 DIMM1.205 DIMM1.206 DIMM2.2 DIMM2.3 DIMM2.8 DIMM2.9 DIMM2.13 DIMM2.14 DIMM2.19 DIMM2.20 DIMM2.25 DIMM2.26 DIMM2.31 DIMM2.32 DIMM2.37 DIMM2.38 DIMM2.43 DIMM2.44 DIMM2.48 DIMM2.49 DIMM2.54 DIMM2.55 DIMM2.60 DIMM2.61 DIMM2.65 DIMM2.66 DIMM2.71 DIMM2.72 DIMM2.127 DIMM2.128 DIMM2.133 DIMM2.134 DIMM2.138 DIMM2.139 DIMM2.144 DIMM2.145 DIMM2.150 DIMM2.151 DIMM2.155 DIMM2.156 DIMM2.161 DIMM2.162 DIMM2.167 DIMM2.168 DIMM2.172 DIMM2.173 DIMM2.178 DIMM2.179 DIMM2.184 DIMM2.185 DIMM2.189 DIMM2.190 DIMM2.195 DIMM2.196 DIMM2.205 DIMM2.206 DIMM3.2 DIMM3.3 DIMM3.8 DIMM3.9 DIMM3.13 DIMM3.14 DIMM3.19 DIMM3.20 DIMM3.25 DIMM3.26 DIMM3.31 DIMM3.32 DIMM3.37 DIMM3.38 DIMM3.43 DIMM3.44 DIMM3.48 DIMM3.49 DIMM3.54 DIMM3.55 DIMM3.60 DIMM3.61 DIMM3.65 DIMM3.66 DIMM3.71 DIMM3.72 DIMM3.127 DIMM3.128 DIMM3.133 DIMM3.134 DIMM3.138 DIMM3.139 DIMM3.144 DIMM3.145 DIMM3.150 DIMM3.151 DIMM3.155 DIMM3.156 DIMM3.161 DIMM3.162 DIMM3.167 DIMM3.168 DIMM3.172 DIMM3.173 DIMM3.178 DIMM3.179 DIMM3.184 DIMM3.185 DIMM3.189 DIMM3.190 DIMM3.195 DIMM3.196 DIMM3.205 DIMM3.206 EC2314.2 EC2323.2 EC2501.2 EC2502.2 EC2503.2 EC2801.2 EC2802.2 EC2803.2 EC2804.2 EC2805.2 EC2806.2 EC2807.2 EC2808.2 EC3401.2 EC3412.2 EC3413.2 EC3414.2 EC4101.1 EC4102.2 EC7612.2 EC7613.2 EC7615.2 EC7616.2 EC7617.2 ED2.2 ED2301.3 ED2301.8 ED2302.3 ED2302.8 ED2303.2 ED2304.2 ED2305.3 ED2305.8 ED2306.3 ED2306.8 ED2307.3 ED2307.8 ED2308.3 ED2308.8 ED2801.2 ED2802.2 ED2804.2 ED2907.2 ED3201.1 ED3202.1 ED3203.2 ED4101.A ED6512.2 ED6513.3 ED6513.8 ED6514.3 ED6514.8 ED6520.2 ED6521.2 FANC1.1 FANC2.1 G1.2 G1901.1 G1902.1 H3301.1 H3301.2 H3301.3 H3301.4 H3301.5 H3301.6 H3301.7 H3301.8 H3302.1 H3302.2 H3302.3 H3302.4 H3302.5 H3302.6 H3302.7 H3302.8 H3303.1 H3303.2 H3303.3 H3303.4 H3303.5 H3303.6 H3303.7 H3303.8 H3304.1 H3304.2 H3304.3 H3304.4 H3304.5 H3304.6 H3304.7 H3304.8 HDMI1.2 HDMI1.5 HDMI1.8 HDMI1.11 HDMI1.17 HDMI1.20 HDMI1.21 HDMI1.22 HDMI1.23 HDMI2.2 HDMI2.5 HDMI2.8 HDMI2.11 HDMI2.17 HDMI2.20 HDMI2.21 HDMI2.22 HDMI2.23 HNGFF1.1 LAN1.33 LEDH1.4 LEDH1.5 LEDH1.8 LEDH1.14 NGFFE1.1 NGFFE1.7 NGFFE1.18 NGFFE1.33 NGFFE1.39 NGFFE1.45 NGFFE1.51 NGFFE1.57 NGFFE1.63 NGFFE1.69 NGFFE1.75 OSC1.2 PC3601.2 PC3602.2 PC3603.2 PC3604.2 PC4201.2 PC4202.2 PC4203.2 PC4204.2 PC4409.2 PC4410.2 PC4415.2 PC4416.2 PC4417.2 PC4418.2 PC4422.2 PC4423.2 PC4424.2 PC4426.2 PC4427.2 PC4428.2 PC4429.2 PC4431.2 PC4509.2 PC4510.2 PC4515.2 PC4516.2 PC4517.2 PC4518.2 PC4522.2 PC4523.2 PC4524.2 PC4526.2 PC4527.2 PC4528.2 PC4529.2 PC4531.2 PC4701.2 PC4702.2 PC4704.2 PC4706.2 PC4707.2 PC4708.2 PC4711.2 PC4801.2 PC4802.2 PC4803.2 PC4804.2 PC4806.2 PC4807.2 PC4808.2 PC4909.2 PC4910.2 PC4912.2 PC4914.2 PC4915.2 PC4916.2 PC4917.2 PC4918.2 PC4919.2 PC4920.2 PC4921.2 PC4922.2 PC4923.2 PC4924.2 PC4925.2 PC4926.2 PC5001.2 PC5003.2 PC5006.2 PC5007.2 PC5009.2 PC5010.2 PC5011.2 PC5012.2 PC5028.2 PC5029.2 PC5030.2 PC5031.2 PC5033.2 PC5034.1 PC5035.2 PC5036.2 PC5037.2 PC5038.2 PC5039.2 PC5041.2 PC5101.2 PC5102.2 PC5103.2 PC5104.2 PC5106.2 PC5108.2 PC5109.2 PC5110.2 PC5111.2 PC5112.2 PC5211.2 PC5212.2 PC5213.2 PC5214.2 PC5216.2 PC5217.2 PC5218.2 PC5219.2 PC5220.2 PC5221.2 PC5222.2 PCIE16.A4 PCIE16.A12 PCIE16.A15 PCIE16.A18 PCIE16.A20 PCIE16.A23 PCIE16.A24 PCIE16.A27 PCIE16.A28 PCIE16.A31 PCIE16.A34 PCIE16.A37 PCIE16.A38 PCIE16.A41 PCIE16.A42 PCIE16.A45 PCIE16.A46 PCIE16.A49 PCIE16.A51 PCIE16.A54 PCIE16.A55 PCIE16.A58 PCIE16.A59 PCIE16.A62 PCIE16.A63 PCIE16.A66 PCIE16.A67 PCIE16.A70 PCIE16.A71 PCIE16.A74 PCIE16.A75 PCIE16.A78 PCIE16.A79 PCIE16.A82 PCIE16.B4 PCIE16.B7 PCIE16.B13 PCIE16.B16 PCIE16.B18 PCIE16.B21 PCIE16.B22 PCIE16.B25 PCIE16.B26 PCIE16.B29 PCIE16.B32 PCIE16.B35 PCIE16.B36 PCIE16.B39 PCIE16.B40 PCIE16.B43 PCIE16.B44 PCIE16.B47 PCIE16.B49 PCIE16.B52 PCIE16.B53 PCIE16.B56 PCIE16.B57 PCIE16.B60 PCIE16.B61 PCIE16.B64 PCIE16.B65 PCIE16.B68 PCIE16.B69 PCIE16.B72 PCIE16.B73 PCIE16.B76 PCIE16.B77 PCIE16.B80 PN4401.2 PN4501.2 PQ4402.1 PQ4402.2 PQ4402.3 PQ4502.1 PQ4502.2 PQ4502.3 PQ4702.1 PQ4702.2 PQ4702.3 PQ4902.1 PQ4902.2 PQ4902.3 PQ4904.1 PQ4904.2 PQ4904.3 PQ5002.1 PQ5002.2 PQ5002.3 PQ5004.1 PQ5004.2 PQ5004.3 PQ5005.1 PQ5005.4 PQ5102.1 PQ5102.2 PQ5102.3 PR3602.2 PR4204.1 PR4205.2 PR4207.2 PR4210.2 PR4211.2 PR4212.2 PR4213.2 PR4215.2 PR4223.2 PR4406.2 PR4409.2 PR4414.2 PR4415.2 PR4431.2 PR4432.2 PR4433.2 PR4506.2 PR4514.2 PR4515.2 PR4531.2 PR4532.2 PR4533.2 PR4702.2 PR4711.2 PR4718.2 PR4720.2 PR4803.2 PR4820.2 PR4916.2 PR4918.2 PR4919.2 PR4921.2 PR4923.2 PR4924.2 PR5002.2 PR5006.2 PR5012.2 PR5017.2 PR5102.2 PR5107.2 PR5110.2 PR5116.2 PR5120.2 PR5211.2 PR5240.2 PR9765.2 PT4401.2 PT4402.2 PT4403.2 PT4491.2 PT4501.2 PT4502.2 PT4503.2 PT4504.2 PT4591.2 PT4701.2 PT4702.2 PT4901.2 PT4902.2 PT4903.2 PT5001.2 PT5002.2 PT5003.2 PT5004.2 PT5005.2 PT5101.2 PT5102.2 PU4202.4 PU4203.4 PU4401.11 PU4401.29 PU4501.11 PU4501.29 PU4701.11 PU4801.1 PU4902.21 PU5001.5 PU5001.11 PU5004.1 PU5004.3 PU5004.14 PU5004.21 PU5101.11 PU5102.2 PU5202.1 Q2001.S Q2707.C Q2709.C Q2711.E Q3402.E Q3409.1 Q3409.4 Q3512.S Q3514.S Q3516.S Q4001.1 Q4001.4 Q4101.1 Q4101.4 Q4201.S Q4202.1 Q4202.4 Q4302.1 Q4302.4 Q4303.1 Q4304.S Q5401.S Q6502.S Q6503.S Q6514.S Q6519.S Q6520.S Q6527.S Q6528.1 Q6528.4 Q6530.1 Q6530.4 Q6531.1 Q6531.4 Q6532.E Q6533.4 Q6540.1 Q6540.4 Q6541.1 Q6541.4 Q6544.S Q6551.E R501.2 R502.2 R511.2 R512.2 R513.2 R514.2 R804.2 R809.2 R1208.2 R1209.2 R1210.2 R1211.2 R1308.2 R1309.2 R1310.2 R1311.2 R1516.2 R1517.2 R1518.2 R1519.2 R1520.2 R1522.2 R1523.2 R1524.2 R1525.2 R1526.2 R1527.2 R1528.2 R1529.2 R1534.1 R1535.1 R1536.1 R1541.2 R1602.2 R1603.2 R1912.2 R1935.1 R1936.1 R1938.1 R1940.1 R1945.2 R2016.2 R2033.2 R2034.2 R2046.1 R2057.1 R2106.1 R2109.2 R2418.2 R2419.2 R2420.2 R2475.2 R2516.2 R2520.2 R2732.2 R2908.2 R2910.2 R3701.1 R3702.1 R3703.1 R3704.1 R4004.2 R4304.2 R4503.2 R4603.2 R4605.2 R4606.2 R4607.2 R4610.2 R4612.2 R4614.2 R5403.2 R6105.1 R6106.2 R6107.2 R6542.2 R6560.2 R6561.2 R6562.2 R6573.2 R9622.1 R9629.2 R9647.1 R9649.2 R9652.2 R9653.2 R9654.2 R9656.2 R9702.2 R9741.2 R9786.2 R9798.1 R9799.1 R9800.1 R9801.1 R9814.2 R9863.2 RN1501.2(A) RN1502.2(A) RN1503.2(A) RN1901.2(A) RN1902.2(A) RN1903.2(A) RN5601.4(B) RN5602.4(B) RN5603.4(B) RN5604.4(B) RN6401.2(A) SATA0.1 SATA0.4 SATA0.7 SATA0.8 SATA0.9 SATA1.1 SATA1.4 SATA1.7 SATA1.8 SATA1.9 SATAP1.3 SATAP1.4 SIO1.54 SPI1.4 SPIH1.1 TC1901.2 TC2501.2 TC4601.2 TC4602.2 TC4603.2 TC4606.2 U3RJ1.4 U3RJ1.7 U3RJ1.13 U3RJ1.16 U3RJ1.G1 U3RJ1.G2 U3RJ1.G3 U3RJ1.G4 U3RJ1.G5 U3RJ1.G6 U3RJ1.G7 U3RJ1.G8 U3RJ1.R10 U2402.2 U2502.4 U2901.3 U2903.3 U3701.2 U3702.2 U3703.2 U3801.2 U4601.29 U4602.1 U4602.2 U4602.3 U4602.4 U5401.11 U5401.15 U6506.11 U6506.13 U6506.14 U6506.16 U6506.18 U6506.33 U6510.3 U6511.3 U6519.1 U6519.2 U6519.4 U6519.7 U6523.1 U6523.4 U6524.1 U6524.4 USB2F1.2 USB2F2.2 USB2F2.3 USB2F2.4 USB2R1.4 USB2R1.8 USB2R1.9 USB2R1.10 USB2R1.11 USB2R1.12 USB3F1.4 USB3F1.7 USB3F1.10 USB3F1.13 USB3F1.16 VGA1.5 VGA1.6 VGA1.7 VGA1.8 VGA1.10 VGA1.16 VGA1.17 X1501.2 X1501.4 X2101.2 X2101.4 X3501.2 X3501.4 X3502.2 X3502.3 XDP1.1 XDP1.2 XDP1.7 XDP1.8 XDP1.13 XDP1.14 XDP1.19 XDP1.20 XDP1.25 XDP1.26 XDP1.31 XDP1.32 XDP1.37 XDP1.38 XDP1.49 XDP1.50 XDP1.59
V1P5_PWR: PC5111.1 PR5109.1 PU5102.5
VBAT: BT1.1 R1515.2
VBAT1: D1501.1 R1515.1
VBAT_SIO: C2017.1 R2015.1 SIO1.29
VCC0_VCC_SEN: CPU1.AD29 CPU1.AG32 PR4408.2 PR4410.1
VCC0_VSS_SEN: CPU1.AF27 CPU1.AJ32 PC4414.1 PR4409.1 PR4411.2
VCC3_3SBREF: PC5112.1 PR3601.2 PR3602.1 PU3601.1
VCC_CORE: C1027.1 C1030.1 C1032.1 C1033.1 C1040.1 C1041.1 C1042.1 C1048.1 C15189.1 C15190.1 CPU1.AF29 CPU1.AF30 CPU1.AF36 CPU1.AG27 CPU1.AG29 CPU1.AG30 CPU1.AG33 CPU1.AG35 CPU1.AG36 CPU1.AG38 CPU1.AJ27 CPU1.AJ29 CPU1.AJ30 CPU1.AJ33 CPU1.AJ36 CPU1.AJ38 PG4402.1 PL4401.2 PR4408.1 PT4401.1 PT4402.1 PT4403.1 R2001.2
VSS5: CPU1.B52
0D675V_S0: C1219.1 C1220.1 C1221.1 C1222.1 C1223.1 C1224.1 C1319.1 C1320.1 C1321.1 C1322.1 C1323.1 C1324.1 DIMM1.203 DIMM1.204 DIMM2.203 DIMM2.204 DIMM3.203 DIMM3.204 PR5027.1
1D05V_LAN: C2106.1 C2107.1 C2108.1 C2109.1 C2110.1 C2111.1 C2114.1 C2115.1 L2101.2 LAN1.3 LAN1.8 LAN1.22 LAN1.30 R2107.2
1D5V_S0: PR5109.2 R6526.1
1D05V_S5: C1001.1 C1002.1 C1003.1 C1004.1 C1005.1 C1006.1 C1007.1 C1008.1 C1009.1 C1010.1 C1011.1 C1012.1 C1013.1 C1017.1 C1018.1 C1020.1 C1022.1 C1024.1 C1025.1 C1056.1 C1057.1 CPU1.AA18 CPU1.AA19 CPU1.AA21 CPU1.AA22 CPU1.AA24 CPU1.AA25 CPU1.AA32 CPU1.AA33 CPU1.AA35 CPU1.AA36 CPU1.AC18 CPU1.AC19 CPU1.AC21 CPU1.AC22 CPU1.AC24 CPU1.AC25 CPU1.AC32 CPU1.AD25 CPU1.AD27 CPU1.AM21 CPU1.AM22 CPU1.AM32 CPU1.AM33 CPU1.AN22 CPU1.AN32 CPU1.G10 CPU1.H10 CPU1.N18 CPU1.U19 CPU1.U22 CPU1.U24 CPU1.U27 CPU1.V18 CPU1.V19 CPU1.V22 CPU1.V24 CPU1.V27 CPU1.V29 CPU1.V33 CPU1.Y30 CPU1.Y32 CPU1.Y33 CPU1.Y35 PC4422.1 PC4522.1 PR4426.1 PR4427.1 PR4526.1 PR4527.1 PR4706.2 PR5215.2 PR5216.2 PR5217.2 PR5218.2 PR5219.2 PR5220.2 PR5221.2 PR9758.2 PR9759.2 R9744.2 R9751.2 R9755.2 R9873.2 R9874.2
1D05V_S5_PG: PC4701.1 PR4712.2 PR4720.1 PU4701.1 R3529.1 R9728.1
1D8V_DDI: R6534.2 R6535.2 R9643.2 R9703.1 R9704.1 RN801.3(B) RN801.4(B) RN5402.3(B) RN5402.4(B)
1D8V_S0: C15188.1 Q6545.D R6519.2 R6520.2 R6532.1 R6565.2 R6574.2 R9704.2
1D8V_S0_EN1: Q6544.D R9842.2 R9843.2
1D8V_S0_EN2: C15186.1 C15187.2 C15188.2 Q6545.G R9843.1
1D8V_S5: C1104.1 C1105.1 C1110.1 C1111.1 C1113.1 C1114.1 C1121.1 C1130.1 C2434.2 C9602.1 C9603.1 C15187.1 CPU1.AA29 CPU1.AD33 CPU1.AF33 CPU1.AK18 CPU1.AK19 CPU1.U16 CPU1.Y18 PR4801.2 PR5210.2 PR5222.2 PR5223.2 PR5224.2 PR5225.2 Q6509.G Q6511.G Q6545.S R1501.1 R1502.1 R1503.1 R1504.1 R1505.1 R1507.1 R1508.1 R1509.1 R1510.1 R1511.1 R1512.1 R1513.1 R1533.1 R1540.1 R1632.2 R1801.2 R1802.2 R1807.2 R1915.2 R1920.1 R1930.2 R1933.2 R1942.1 R1943.1 R1944.1 R2474.1 R2522.2 R6404.2 R6507.1 R6533.1 R6558.2 R6559.2 R9620.1 R9660.1 R9662.1 R9671.2 R9672.2 R9674.2 R9703.2 R9733.1 R9734.1 R9742.2 R9743.2 R9788.1 R9792.1 R9842.1 R9845.1 R9846.1 R9849.1 R9852.2 R9855.1 R9859.1 R9864.2 R9867.1 R9879.2 U2402.1 XDP1.43 XDP1.44
1D8V_S5_PG: PC5103.1 PR5115.2 PR5120.1 PU5101.1 R9729.1 R9731.1
1D8V_SPI: C2506.1 C2507.2 R2522.1 RN2501.3(B) RN2501.4(B) RN2502.3(B) RN2502.4(B) SPI1.8 U2502.8
1D15V_S5: C1026.1 C1034.1 C1035.1 C1037.1 C1047.1 CPU1.AJ35 CPU1.AK21 CPU1.AK30 CPU1.AK33 CPU1.AK35 CPU1.AK36 CPU1.AM19 CPU1.AM29 PR4804.2
1D15V_S5_PG: D3403.1 PC4801.1 PR4805.2 PR4820.1 PR5229.2 PU4801.7
1D24V_S5: C1116.1 C1128.1 C1134.1 C1137.1 C1138.1 CPU1.AC30 CPU1.AC36 CPU1.AD35 CPU1.AD38 CPU1.AF35 CPU1.M41 CPU1.P38 CPU1.P40 CPU1.P41 CPU1.T40 CPU1.U35 CPU1.V30 CPU1.V35 CPU1.V36 CPU1.Y25 CPU1.Y27 CPU1.Y36 PR5213.2 R2130.2
1D24V_S5_PG: PC5211.1 PR5231.2 PR5240.1 PU5202.7 R3528.1
1D35V_DDR: PC5029.1 PC5032.1 PL5001.2 PR5025.1 PR5026.1 PR5028.1 PR5033.1 PR5034.2 PR5035.2 PR5036.1 PR5038.1 PR5041.1 PT5001.1 PT5002.1
1D35V_S3: C1120.1 C1122.1 C1123.1 C1124.1 C1201.1 C1202.1 C1203.1 C1204.1 C1205.1 C1206.1 C1207.1 C1208.1 C1209.1 C1210.1 C1211.1 C1212.1 C1213.1 C1214.1 C1215.1 C1216.1 C1230.1 C1231.1 C1301.1 C1302.1 C1303.1 C1304.1 C1305.1 C1306.1 C1307.1 C1308.1 C1309.1 C1310.1 C1311.1 C1312.1 C1313.1 C1314.1 C1315.1 C1316.1 C1330.1 C1331.1 CPU1.AM18 CPU1.AM36 CPU1.AN18 CPU1.AN19 CPU1.AN35 CPU1.AN36 CPU1.AU18 CPU1.AU36 CPU1.AV10 CPU1.AV16 CPU1.AV38 CPU1.AV44 CPU1.AY10 CPU1.AY44 CPU1.BE1 CPU1.BE3 CPU1.BE51 CPU1.BE53 CPU1.BG3 CPU1.BG51 CPU1.BH4 CPU1.BH5 CPU1.BH49 CPU1.BH50 CPU1.BJ2 CPU1.BJ3 CPU1.BJ5 CPU1.BJ49 CPU1.BJ51 CPU1.BJ52 DIMM1.75 DIMM1.76 DIMM1.81 DIMM1.82 DIMM1.87 DIMM1.88 DIMM1.93 DIMM1.94 DIMM1.99 DIMM1.100 DIMM1.105 DIMM1.106 DIMM1.111 DIMM1.112 DIMM1.117 DIMM1.118 DIMM1.123 DIMM1.124 DIMM2.75 DIMM2.76 DIMM2.81 DIMM2.82 DIMM2.87 DIMM2.88 DIMM2.93 DIMM2.94 DIMM2.99 DIMM2.100 DIMM2.105 DIMM2.106 DIMM2.111 DIMM2.112 DIMM2.117 DIMM2.118 DIMM2.123 DIMM2.124 DIMM3.75 DIMM3.76 DIMM3.81 DIMM3.82 DIMM3.87 DIMM3.88 DIMM3.93 DIMM3.94 DIMM3.99 DIMM3.100 DIMM3.105 DIMM3.106 DIMM3.111 DIMM3.112 DIMM3.117 DIMM3.118 DIMM3.123 DIMM3.124 PR5025.2 PR5026.2 PR5028.2 PR5033.2 PR5036.2 PR5038.2 R503.1 R504.1 R505.1 R506.1 R1202.1 R1203.1 R1304.1 R1305.1 R2002.2 R6528.2 R6529.2 R9768.1 R9770.1
1D35V_S3_PG: PR5032.2 PU5004.10 R9773.1 R9828.1 R9830.1 R9837.1 R9838.1
1P05V_A: PC4705.1 PC4707.1 PC4708.1 PL4701.2 PR4706.1 PR5215.1 PR5216.1 PR5217.1 PR5218.1 PR5219.1 PR5220.1 PR5221.1 PR9766.1 PT4701.1
1P15V_A: PC4805.1 PC4806.1 PC4807.1 PC4808.1 PR4804.1 PR4806.1 PU4801.3 PU4801.4
3.3_POP: Q2707.B Q2709.E Q2712.C R2720.1
3D3V_LAN: C2104.1 C2105.1 C2119.1 C2120.1 ED2802.5 ED2804.5 ED3203.5 LAN1.11 LAN1.32 R2102.2 R2103.2 R2104.2 R2112.2 R2113.2 R2801.2 R2810.2 R2811.2 RN1902.1(A)
3D3V_NGFF: C6101.1 C6102.1 C6103.1 C6104.1 NGFFE1.2 NGFFE1.4 NGFFE1.72 NGFFE1.74 R6103.1
3D3V_RTD2168: C15149.2 C15150.2 L5311.1 L5312.1 R5801.2 R9644.2 R9648.1 R9650.1 R9651.1 R9655.1 R9657.1 R9811.2 R9812.2 R9813.2 U6506.5 U6506.20 U6519.3 U6519.8
3D3V_S0: ATX1.1 ATX1.2 ATX1.12 ATX1.13 ATX2.1 ATX2.2 ATX2.11 AUDIO1.1 C1217.1 C1218.1 C1317.1 C1318.1 C1902.1 C1906.1 C1907.1 C1908.1 C2003.1 C2004.1 C2208.1 C2209.1 C2435.2 C5409.1 C5419.1 D2502.K DBGH1.14 DIMM1.199 DIMM2.199 DIMM3.199 EC3409.1 EC3413.1 OSC1.4 PCIE16.A9 PCIE16.A10 PCIE16.B8 PR4401.1 PR4501.1 PR5015.1 PR5229.1 Q6510.G Q6512.G R1201.2 R1204.1 R1205.1 R1301.2 R1302.1 R1303.1 R1634.2 R2013.2 R2024.2 R2025.2 R2027.2 R2028.2 R2029.1 R2030.1 R2031.1 R2032.1 R2035.1 R2036.1 R2037.1 R2038.2 R2042.2 R2043.2 R2054.2 R2056.1 R2108.2 R2223.2 R2510.1 R3202.1 R3424.1 R4006.2 R9644.1 R9663.1 R9664.1 R9675.2 R9739.1 R9740.1 R9818.1 R9850.1 R9851.1 R9882.1 RN1502.1(A) RN1503.1(A) RN5601.3(B) RN5602.3(B) RN5603.3(B) RN5604.3(B) RN6401.1(A) SIO1.53 U2402.6 U5401.13 U5401.14
3D3V_S5_PRIME: C1103.1 C1115.1 C1133.1 C1905.1 C2709.2 C3502.1 CPU1.B22 CPU1.C23 CPU1.D4 CPU1.E3 CPU1.G1 ED3202.2 PCIE16.B10 PR5032.1 Q2706.E Q3510.D Q3511.D Q6550.G R2004.1 R2022.2 R2041.2 R2047.2 R2050.2 R2051.2 R2102.1 R2104.1 R2720.2 R2722.2 R3419.1 R4005.1 R5004.1 R5801.1 R6101.2 R6102.2 R6103.2 R6527.1 R9611.2 R9723.2 R9724.2 R9766.1 R9767.1 R9769.1 R9771.1 R9790.2 R9847.1 R9848.1 R9861.2 R9872.1 RN1501.1(A) RN1901.1(A) RN1903.1(A) RN5407.3(B) RN5407.4(B) RN5408.3(B) RN5408.4(B) RN5409.3(B) RN5409.4(B)
3D3V_S5_PRIME_EN1: Q6527.D R3517.2 R3518.1 R4308.2
3D3V_S5_PRIME_EN2: C3501.1 C3502.2 C3505.2 Q3510.G Q3511.G R3518.2
3D3V_S5_PRIME_EN3: Q6527.G R3528.2 R3529.2
3D3V_SB: C2012.1 C2040.1 C3505.1 C5416.1 C5417.1 D1501.2 PC3603.1 PC3604.1 PR3601.1 PR4225.2 PR4906.1 PR4908.1 PR4910.1 PR4922.1 PR5108.1 PU3601.2 Q3403.G Q3510.S Q3511.S R1226.1 R2045.2 R2048.2 R2049.2 R3409.1 R3414.1 R3527.1 R4307.2 R5401.2 R9661.1 R9723.1 R9724.1 R9725.1 RN5411.3(B) SIO1.11 U5401.1 U5401.2
+3D3V_PWR: PC4909.1 PG4902.2 PL4903.1 PR4906.2 PR4908.2 PR4910.2 PT4902.1
+DCBATOUT_RT8243_1: PC4919.1 PC4920.1 PC4921.1 PC4922.1 PC4923.1 PC4924.1 PC4925.1 PL4901.2 PL4902.2 PQ4901.5 PQ4901.6 PQ4901.7 PQ4901.8 PQ4903.5 PQ4903.6 PQ4903.7 PQ4903.8 PR4925.1 PT4901.1 PU4902.11
AC_PRESENT_CPU: CPU1.C13 R9672.1
AD_JK_S: DCIN1.1 EC4101.2 EC4102.1 ED4101.K PC4205.1 PR4214.2 PU4201.1 PU4201.2 PU4201.3
AD_JK_S_R: PC4204.1 PR4201.1 PR4211.1 PR4212.1 PR4217.1 PR4220.1 PR4221.1 PR4224.1 PR4226.1 PU4201.5 PU4201.6 PU4201.7 PU4201.8
ADP_12V_S0_PG: PC5003.1 PR5015.2 PU5001.10 R4002.1
ADP_EUPPWR_EN1: Q4302.2 Q4304.D R4307.1
ADP_EUPPWR_EN2: Q4301.E R4301.2
ADP_EUPPWR_EN3: Q4301.B R4303.2 R4306.1
ADP_EUPPWR_EN4: Q4302.5 Q4302.6 R4306.2
ADP_EUPPWR_EN5: C4301.1 C4302.2 Q4301.C R4302.1 R4304.1 R4305.1
ADP_EUPPWR_EN6: Q4302.3 R4305.2
ADP_EUPPWR_EN7: C4303.1 R4302.2 U4301.4
ADP_NORMPWR_EN: C5411.1 Q5401.D R5401.1 U5401.3 U5401.5
ADP_OCP: PR4208.1 PU4202.1
ANTI-POP_GPIO1: AUDIO1.4 R2725.1
ANTI-POP_GPIO1_L: AUDIO1.3 C2220.1
ANTI-POP_GPIO1_R: Q2709.B R2725.2 R2726.2
APU_SIC: SIO1.26 TP2402.1
APU_SID: SIO1.25 TP2401.1
ATX_ON1*: Q3402.B R3407.1
ATX_ON*: ATX1.16 ATX2.14 C3402.1 Q3402.C R3403.2 R3404.2
ATX_PWRGD: ATX1.8 ATX2.8 C3408.1 D3401.A D3402.2 D3404.2 PR5232.1 R3405.2 R3525.2 R4001.1 R9737.1
ATX_PWRGD_SIO: Q4001.3 R2038.1 R4001.2 R4002.2 R4006.1 SIO1.6
AUD_IN_L: AUDIO1.23 TC2702.1
AUD_IN_LL: L2702.1 Q2704.6 R2702.2
AUD_IN_LL*: Q2704.2 R2714.2
AUD_IN_LL_1: R2702.1 TC2702.2
AUD_IN_R: AUDIO1.24 TC2703.1
AUD_IN_RR: L2703.1 Q2704.3 R2703.2
AUD_IN_RR*: Q2704.5 R2716.2
AUD_IN_RR_1: R2703.1 TC2703.2
AUD_MIC1_L: AUDIO1.21 TC2705.1
AUD_MIC1_LL: L2701.1 Q2701.6 R2712.2 R2713.2
AUD_MIC1_LL*: Q2701.2 R2701.2
AUD_MIC1_LL_1: R2713.1 TC2705.2
AUD_MIC1_R: AUDIO1.22 TC2706.1
AUD_MIC1_RR: L2706.1 Q2701.3 R2715.2 R2717.2
AUD_MIC1_RR*: Q2701.5 R2723.2
AUD_MIC1_RR_1: R2715.1 TC2706.2
AUD_MIC_1L: AUDR1.2 C2706.1 D2706.2 L2701.2
AUD_MIC_1R: AUDR1.5 C2705.1 D2706.1 L2706.2
AUDAMPIN_L: AUDIO1.35 TC2701.1
AUDAMPIN_L_C: R2706.1 TC2701.2
AUDAMPIN_R: AUDIO1.36 TC2704.1
AUDAMPIN_R_C: R2707.1 TC2704.2
AUDIN_L: AUDR1.32 C2703.1 D2704.2 L2702.2
AUDIN_R: AUDR1.35 C2702.1 D2704.1 L2703.2
AUDIO_VREF: AUDIO1.27 C2218.1 C2219.1
AZRST: Q2712.B R2734.1
BLAN_XTALI: LAN1.28 R2114.2 R2121.2
BLAN_XTALI_1: C2117.2 R2121.1 X2101.1
BLAN_XTALO: C2116.2 LAN1.29 R2114.1 X2101.3
BOARD1: R2042.1 R2046.2 SIO1.55
BVCCRTC_EXTPAD: C1903.1 CPU1.F16
BZ_ON: Q2711.C R2729.2 R2731.2
BZ_ON1: BUZ1.2 R2729.1 R2731.1
CFG0: CPU1.AM40 XDP1.9
CFG1: CPU1.AM41 XDP1.11
CFG2: CPU1.AM44 Q6553.E R9866.2 R9879.1 XDP1.15
CFG3: CPU1.AM45 XDP1.17
CFG4: CPU1.AM47 Q1906.C R1632.1 XDP1.27
CFG5: CPU1.AK48 XDP1.29
CFG6: CPU1.AM48 XDP1.33
CFG7: CPU1.AK41 XDP1.35
CFG8: CPU1.AK42 XDP1.21
CIIC_SCL: Q6543.1 R9650.2 R9652.1 R9809.2 U6506.2
CIIC_SDA: Q6543.4 R9651.2 R9653.1 R9810.2 U6506.3
CLK_PCI_DEBUG: DBGH1.6 EC7617.1 R1903.1
CLK_PCIE_GFX_N0: CPU1.C21 PCIE16.A14
CLK_PCIE_GFX_P0: CPU1.A21 PCIE16.A13
CLK_PCIE_LAN_N3: CPU1.A17 LAN1.16
CLK_PCIE_LAN_P3: CPU1.C17 LAN1.15
CLK_PCIE_WLAN_N2: CPU1.B18 NGFFE1.49
CLK_PCIE_WLAN_P2: CPU1.C18 NGFFE1.47
CLKIN: R9815.2 R9816.2 SIO1.24
COPEN_N: R2016.1 SIO1.28
COREPWROK: CPU1.G16 R9606.1 R9765.2 R9786.1
CPU_FAN_PWM1: R2513.1 SIO1.4
CPU_FAN_TACH1: C2005.1 R2519.2 SIO1.3
CPU_VSS2: CPU1.A6 TP9906.1
CPU_VSS16: CPU1.BH53 TP9905.1
CRT_B: C5311.1 ED6520.4 L5303.2 VGA1.3
CRT_DDCCLK_CON: C5303.1 ED2.1 R2413.2 VGA1.15
CRT_DDCDATA_CON: C5306.1 ED2.3 R2412.2 VGA1.12
CRT_G: C5310.1 ED6520.3 L5302.2 VGA1.2
CRT_HSYNC_CON: C5304.1 ED2.4 R9658.1 VGA1.13
CRT_R: C5309.1 ED6520.1 L5301.2 VGA1.1
CRT_VSYNC_CON: C5305.1 ED2.6 R9659.1 VGA1.14
DDI0_RCOMP_N: CPU1.G38 R801.1
DDI0_RCOMP_P: CPU1.F38 R801.2
DDI1_RCOMP_N: CPU1.F49 R802.1
DDI1_RCOMP_P: CPU1.F47 R802.2
DDR3_DRAM_PWROK: CPU1.AV28 R9770.2 U6524.6
DDR3_DRAM_PWROK1: R9771.2 U6524.2 U6524.3
DDR3_DRAM_PWROK2: R9772.2 R9773.2 U6524.5
DDR3_VCCA_PWRGD_3D3V: R9764.2 U6523.5
DDR3_VCCA_PWROK: CPU1.AV26 R9768.2 U6523.6
DDR3_VCCA_PWROK1: R9769.2 U6523.2 U6523.3
DDR_1D35VIN: PC5038.1 PC5039.1 PL4801.1 PL5002.1 PL5003.1 PQ5001.5 PQ5001.6 PQ5001.7 PQ5001.8 PR5031.1 PT5003.1
DIMM1_DRAMRST#: C1327.1 DIMM1.30 R1316.1
DIMM1_VREF_CA: C1325.1 DIMM1.126 R1306.1
DIMM1_VREF_CA_R: R1304.2 R1306.2 R1310.1
DIMM1_VREF_DQ: C1326.1 DIMM1.1 R1307.1
DIMM1_VREF_DQ_R: R1305.2 R1307.2 R1311.1
DIMM2_DRAMRST#: C1227.1 DIMM2.30 DIMM3.30 R1216.1
DIMM2_VREF_CA: C1225.1 DIMM2.126 DIMM3.126 R1206.1
DIMM2_VREF_CA_R: R1202.2 R1206.2 R1210.1
DIMM2_VREF_DQ: C1226.1 DIMM2.1 DIMM3.1 R1207.1
DIMM2_VREF_DQ_R: R1203.2 R1207.2 R1211.1
DISCHARGE_A: Q4101.6 R3423.2
DISCHARGE_B: Q3409.3 R3425.2
DISCHARGE_C: Q3409.6 R3424.2
DISCHARGE_M: Q3409.2 Q3409.5 Q4101.2 Q4101.3 R3411.2
DP_AUX_CPU_N: C15146.1 CPU1.K42
DP_AUX_CPU_P: C15145.1 CPU1.M42
DP_AUX_RTD2168_N: C15146.2 U6506.27
DP_AUX_RTD2168_P: C15145.2 U6506.26
DP_DATA_CPU_N0: C15142.1 CPU1.H51
DP_DATA_CPU_N1: C15144.1 CPU1.K52
DP_DATA_CPU_P0: C15141.1 CPU1.J51
DP_DATA_CPU_P1: C15143.1 CPU1.K51
DP_DATA_RTD2168_N0: C15142.2 U6506.30
DP_DATA_RTD2168_N1: C15144.2 U6506.32
DP_DATA_RTD2168_P0: C15141.2 U6506.29
DP_DATA_RTD2168_P1: C15143.2 U6506.31
DP_HPD_CPU#: CPU1.R51 Q6520.D R9643.1 R9645.2
DP_HPD_RTD2168: Q6520.G R9645.1 R9702.1 U6506.1
DSW_EUP_SEL: R2049.1 SIO1.23
EAPD_DEPOP: AUDIO1.47 R2726.1
EDM_SOC: CPU1.M13 R1936.2
EEPROM_WP: R4609.2 R4610.1 U4602.7
FB_AUDOUT_L: AUDR1.22 C2704.1 D2705.2 L2704.2
FB_AUDOUT_R: AUDR1.25 C2701.1 D2705.1 L2705.2
FB_AUDOUTR_L: L2704.1 Q2705.6 R2706.2 R2710.1
FB_AUDOUTR_L*: Q2705.2 R2718.2
FB_AUDOUTR_R: L2705.1 Q2705.3 R2707.2 R2709.1
FB_AUDOUTR_R*: Q2705.5 R2719.2
FP_AUDIO_PRESENCE*_C: AUDH1.3 C2229.1 R2223.1 R2225.1
FP_AUDIO_PRESENCE_N: Q1906.E R1634.1 R2225.2
FP_AUDIO_PRESENCE_N_1: Q1906.B RN1502.3(B) RN1502.4(B)
FP_MIC2_L: AUDIO1.16 TC2202.1
FP_MIC2_L_C: R2220.1 TC2202.2
FP_MIC2_R: AUDIO1.17 TC2201.1
FP_MIC2_R_C: R2221.1 TC2201.2
FP_MICVREF_D1: D2201.2 R2214.1
FP_MICVREF_D2: D2201.1 R2218.1
FP_OUT_L: AUDIO1.14 TC2203.1
FP_OUT_L_C: R2222.1 TC2203.2
FP_OUT_LL*: Q2702.2 R2704.2
FP_OUT_R: AUDIO1.15 TC2204.1
FP_OUT_R_C: R2224.1 TC2204.2
FP_OUT_RR*: Q2702.5 R2705.2
FP_OUTR_L: AUDH1.10 C2231.1 R9796.2
FP_OUTR_LL: Q2702.6 R2222.2 R2229.2 R2231.1 R9796.1
FP_OUTR_R: AUDH1.6 C2230.1 R9797.2
FP_OUTR_RR: Q2702.3 R2224.2 R2226.2 R2230.1 R9797.1
FP_OUTR_SENSE: AUDH1.8 R2204.2 R2228.1
FP_RESET*_R: LEDH1.7 R3406.2
FRONT_JD: AUDR1.23 D2703.A R2205.1
GFX_CLKREQ_CPU#: PCIE16.B17 Q6547.E R9850.2 R9854.2
GFX_CLKREQ_CPU#_1D8: CPU1.AM10 Q6547.C R1801.1 R6520.1 R9849.2 R9854.1
GFX_CORE: C1031.1 C1043.1 C1044.1 C1045.1 C1046.1 C1049.1 CPU1.AD16 CPU1.AD18 CPU1.AD19 CPU1.AF16 CPU1.AF18 CPU1.AF19 CPU1.AF21 CPU1.AF22 CPU1.AG16 CPU1.AG18 CPU1.AG19 CPU1.AG21 CPU1.AG22 CPU1.AG24 CPU1.AJ19 CPU1.AJ21 CPU1.AJ22 CPU1.AJ24 CPU1.AK24 PG4502.1 PL4501.2 PR9764.1 PT4501.1 PT4502.1 PT4503.1 PT4504.1
GFX_REQ#_Q_B: Q6547.B R9851.2
GP_CAMERASB00: CPU1.AB41 XDP1.10
GP_CAMERASB01: CPU1.AB45 XDP1.12
GP_CAMERASB02: CPU1.AB44 XDP1.16
GP_CAMERASB03: CPU1.AC53 XDP1.18
GP_CAMERASB04: CPU1.AB51 XDP1.28
GP_CAMERASB05: CPU1.AB52 XDP1.30
GP_CAMERASB06: CPU1.AA51 XDP1.34
GP_CAMERASB07: CPU1.AB40 XDP1.36
GP_CAMERASB08: CPU1.Y44 R1512.2 R1527.1 XDP1.4
GP_CAMERASB09: CPU1.Y42 R1513.2 R1528.1
GP_CAMERASB11: CPU1.V40 R1529.1 R6507.2
GPIO_RCOMP18: CPU1.AH40 R1536.2
GPIO_SUS1: CPU1.AD52 R1502.2 R1517.1
GPIO_SUS2: CPU1.AH50 R1503.2 R1518.1 R1909.1
GPIO_SUS3: CPU1.AH48 R1504.2 R1519.1
GPIO_SUS4: CPU1.AH51 R1505.2 R1520.1 R1907.1
GPIO_SUS5: CPU1.AH52 TXE1.2
H_PROCHOT#: PR9742.1 PR9757.1 Q4201.D R1937.1
H_PROCHOT#_R: CPU1.AD50 R1930.1 R1937.2
HD_LED_PWR: LEDH1.1 R3402.1
HDA_BITCLK_CODEC: AUDIO1.6 C2206.1 R6510.2
HDA_BITCLK_CPU: CPU1.AD9 R6510.1
HDA_RST#_CODEC: AUDIO1.11 C1803.1 Q2712.E R2733.1 R6511.2
HDA_RST#_CPU: CPU1.AF13 R6511.1
HDA_SDIN0_CODEC: AUDIO1.8 R6512.1
HDA_SDIN0_CPU: C2210.1 CPU1.AD7 R6512.2
HDA_SDOUT_CODEC: AUDIO1.5 R6508.2
HDA_SDOUT_CPU: CPU1.AF14 R6508.1
HDA_SPKR: CPU1.H4 R2730.2 R2732.1
HDA_SYNC_CODEC: AUDIO1.10 R6509.2
HDA_SYNC_CPU: CPU1.AF12 R6509.1
HDMI1_CLK_CON_N: C5408.2 ED2302.5 ED2302.6 EL5604.3 EL5604.4 HDMI1.12 R5606.2 R9688.1
HDMI1_CLK_CON_P: C5407.2 ED2302.4 ED2302.7 EL5604.1 EL5604.2 HDMI1.10 R5606.1 R9687.1
HDMI1_CLK_CPU_N: C5408.1 CPU1.G52
HDMI1_CLK_CPU_P: C5407.1 CPU1.G53
HDMI1_DATA_CON_N0: C5402.2 ED2302.2 ED2302.9 EL5603.3 EL5603.4 HDMI1.9 R5605.2 R9682.1
HDMI1_DATA_CON_N1: C5404.2 ED2301.5 ED2301.6 EL5602.3 EL5602.4 HDMI1.6 R5604.2 R9684.1
HDMI1_DATA_CON_N2: C5406.2 ED2301.2 ED2301.9 EL5601.3 EL5601.4 HDMI1.3 R5603.2 R9686.1
HDMI1_DATA_CON_P0: C5401.2 ED2302.1 ED2302.10 EL5603.1 EL5603.2 HDMI1.7 R5605.1 R9681.1
HDMI1_DATA_CON_P1: C5403.2 ED2301.4 ED2301.7 EL5602.1 EL5602.2 HDMI1.4 R5604.1 R9683.1
HDMI1_DATA_CON_P2: C5405.2 ED2301.1 ED2301.10 EL5601.1 EL5601.2 HDMI1.1 R5603.1 R9685.1
HDMI1_DATA_CPU_N0: C5402.1 CPU1.F52
HDMI1_DATA_CPU_N1: C5404.1 CPU1.H50
HDMI1_DATA_CPU_N2: C5406.1 CPU1.C51
HDMI1_DATA_CPU_P0: C5401.1 CPU1.F53
HDMI1_DATA_CPU_P1: C5403.1 CPU1.H49
HDMI1_DATA_CPU_P2: C5405.1 CPU1.D50
HDMI1_DDCCLK_CON: EC2314.1 ED2303.3 HDMI1.15 Q6515.D R1.2
HDMI1_DDCCLK_CPU: CPU1.Y51 Q6515.S RN801.1(A)
HDMI1_DDCCLK_G: Q6515.G RN5601.1(A) RN5601.2(A)
HDMI1_DDCDATA_CON: EC2323.1 ED2303.4 HDMI1.16 Q6516.D R2.2
HDMI1_DDCDATA_CPU: CPU1.Y52 Q6516.S RN801.2(A)
HDMI1_DDCDATA_G: Q6516.G RN5602.1(A) RN5602.2(A)
HDMI1_HPD_CON: ED2303.1 HDMI1.19 Q6502.G R5403.1 R6556.1
HDMI1_HPD_CPU#: CPU1.W51 Q6502.D R6534.1 R6556.2
HDMI1_LS_R: Q6514.D R9681.2 R9682.2 R9683.2 R9684.2 R9685.2 R9686.2 R9687.2 R9688.2
HDMI2_CLK_CON_N: C15164.2 ED2305.5 ED2305.6 EL5608.3 EL5608.4 HDMI2.12 R5610.2 R9698.1
